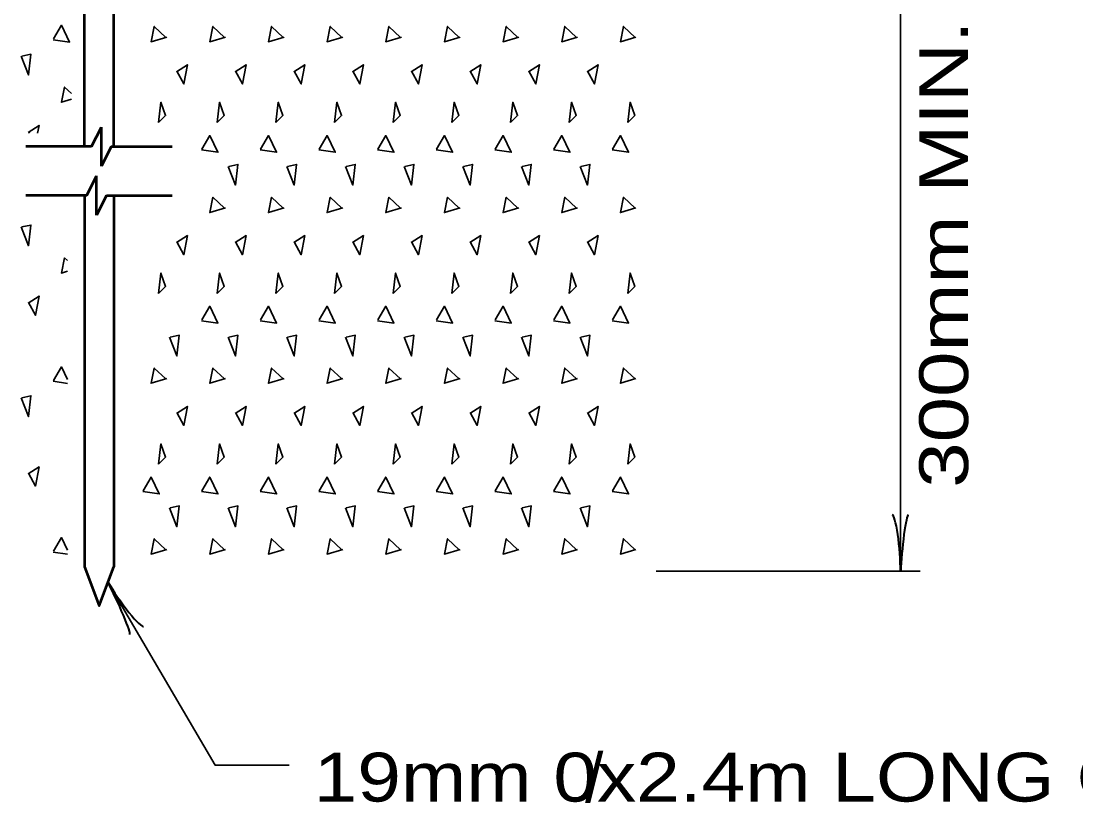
# Model space of a CAD drawing. Extents: x 918 to 1774, y -8 to 536.
# Drawn here: x 1102.6 to 1167.4, y 94.3 to 142.4 of the extents above; entities that cross this region are included whole.
import ezdxf

# ---------------------------------------------------------------- set-up
doc = ezdxf.new("R2010")
doc.units = 0
doc.header["$LTSCALE"] = 1.2
doc.layers.add('1', color=7, linetype='Continuous', lineweight=35)

msp = doc.modelspace()

# ---------------------------------------------------------------- linework, layer by layer
at = {"layer": '1', "lineweight": 53}
for p, q in [((1108.328, 134.643), (1108.328, 176.343)), ((1106.977, 134.643), (1107.578, 135.843)), ((1107.578, 133.443), (1107.578, 135.843)), ((1106.977, 134.643), (1102.928, 134.643)), ((1108.178, 134.643), (1107.578, 133.443)), ((1108.178, 134.643), (1111.928, 134.643)), ((1106.678, 131.643), (1107.278, 132.843)), ((1107.278, 130.443), (1107.278, 132.843)), ((1106.678, 131.643), (1102.928, 131.643)), ((1106.528, 131.643), (1106.528, 108.843)), ((1107.878, 131.643), (1107.278, 130.443)), ((1107.878, 131.643), (1111.928, 131.643)), ((1108.328, 131.643), (1108.328, 108.843))]:
    msp.add_line(p, q, dxfattribs=at)
at = {"layer": '1'}
for p, q in [((1103.102, 135.567), (1103.157, 135.466)), ((1105.493, 120.106), (1104.614, 120.231)), ((1105.493, 109.618), (1104.614, 109.743)), ((1141.628, 108.575), (1157.828, 108.575))]:
    msp.add_line(p, q, dxfattribs=at)
for points in [[(1156.628, 235.047), (1156.628, 170.643), (1156.628, 158.067), (1156.628, 146.075), (1156.628, 108.575)], [(1104.638, 141.255), (1105.118, 142.095), (1105.622, 141.063), (1104.614, 141.207)], [(1111.586, 141.375), (1110.626, 141.087), (1110.818, 142.023), (1111.538, 141.351)], [(1115.186, 141.375), (1114.226, 141.087), (1114.418, 142.023), (1115.138, 141.351)], [(1118.786, 141.375), (1117.826, 141.087), (1118.018, 142.023), (1118.738, 141.351)], [(1122.386, 141.375), (1121.426, 141.087), (1121.618, 142.023), (1122.338, 141.351)], [(1125.986, 141.375), (1125.026, 141.087), (1125.218, 142.023), (1125.938, 141.351)], [(1129.586, 141.375), (1128.626, 141.087), (1128.818, 142.023), (1129.538, 141.351)], [(1133.186, 141.375), (1132.226, 141.087), (1132.418, 142.023), (1133.138, 141.351)], [(1136.786, 141.375), (1135.826, 141.087), (1136.018, 142.023), (1136.738, 141.351)], [(1140.386, 141.375), (1139.426, 141.087), (1139.618, 142.023), (1140.338, 141.351)], [(1102.646, 140.199), (1103.102, 139.047), (1103.246, 140.319), (1102.694, 140.199)], [(1112.21, 139.287), (1112.642, 138.495), (1112.858, 139.671), (1112.186, 139.239)], [(1115.81, 139.287), (1116.242, 138.495), (1116.458, 139.671), (1115.786, 139.239)], [(1119.41, 139.287), (1119.842, 138.495), (1120.058, 139.671), (1119.386, 139.239)], [(1123.01, 139.287), (1123.442, 138.495), (1123.658, 139.671), (1122.986, 139.239)], [(1126.61, 139.287), (1127.042, 138.495), (1127.258, 139.671), (1126.586, 139.239)], [(1130.21, 139.287), (1130.642, 138.495), (1130.858, 139.671), (1130.186, 139.239)], [(1133.81, 139.287), (1134.242, 138.495), (1134.458, 139.671), (1133.786, 139.239)], [(1137.41, 139.287), (1137.842, 138.495), (1138.058, 139.671), (1137.386, 139.239)], [(1105.74, 137.554), (1105.118, 137.367), (1105.31, 138.303), (1105.74, 137.902)], [(1103.661, 135.466), (1103.75, 135.951), (1103.078, 135.519)], [(1113.746, 134.487), (1114.226, 135.327), (1114.73, 134.295), (1113.722, 134.439)], [(1117.346, 134.487), (1117.826, 135.327), (1118.33, 134.295), (1117.322, 134.439)], [(1120.946, 134.487), (1121.426, 135.327), (1121.93, 134.295), (1120.922, 134.439)], [(1124.546, 134.487), (1125.026, 135.327), (1125.53, 134.295), (1124.522, 134.439)], [(1128.146, 134.487), (1128.626, 135.327), (1129.13, 134.295), (1128.122, 134.439)], [(1131.746, 134.487), (1132.226, 135.327), (1132.73, 134.295), (1131.722, 134.439)], [(1135.346, 134.487), (1135.826, 135.327), (1136.33, 134.295), (1135.322, 134.439)], [(1138.946, 134.487), (1139.426, 135.327), (1139.93, 134.295), (1138.922, 134.439)], [(1115.354, 133.431), (1115.81, 132.279), (1115.954, 133.551), (1115.402, 133.431)], [(1118.954, 133.431), (1119.41, 132.279), (1119.554, 133.551), (1119.002, 133.431)], [(1122.554, 133.431), (1123.01, 132.279), (1123.154, 133.551), (1122.602, 133.431)], [(1126.154, 133.431), (1126.61, 132.279), (1126.754, 133.551), (1126.202, 133.431)], [(1129.754, 133.431), (1130.21, 132.279), (1130.354, 133.551), (1129.802, 133.431)], [(1133.354, 133.431), (1133.81, 132.279), (1133.954, 133.551), (1133.402, 133.431)], [(1136.954, 133.431), (1137.41, 132.279), (1137.554, 133.551), (1137.002, 133.431)], [(1115.186, 130.887), (1114.226, 130.599), (1114.418, 131.535), (1115.138, 130.863)], [(1118.786, 130.887), (1117.826, 130.599), (1118.018, 131.535), (1118.738, 130.863)], [(1122.386, 130.887), (1121.426, 130.599), (1121.618, 131.535), (1122.338, 130.863)], [(1125.986, 130.887), (1125.026, 130.599), (1125.218, 131.535), (1125.938, 130.863)], [(1129.586, 130.887), (1128.626, 130.599), (1128.818, 131.535), (1129.538, 130.863)], [(1133.186, 130.887), (1132.226, 130.599), (1132.418, 131.535), (1133.138, 130.863)], [(1136.786, 130.887), (1135.826, 130.599), (1136.018, 131.535), (1136.738, 130.863)], [(1140.386, 130.887), (1139.426, 130.599), (1139.618, 131.535), (1140.338, 130.863)], [(1102.646, 129.711), (1103.102, 128.559), (1103.246, 129.831), (1102.694, 129.711)], [(1112.21, 128.799), (1112.642, 128.007), (1112.858, 129.183), (1112.186, 128.751)], [(1115.81, 128.799), (1116.242, 128.007), (1116.458, 129.183), (1115.786, 128.751)], [(1119.41, 128.799), (1119.842, 128.007), (1120.058, 129.183), (1119.386, 128.751)], [(1123.01, 128.799), (1123.442, 128.007), (1123.658, 129.183), (1122.986, 128.751)], [(1126.61, 128.799), (1127.042, 128.007), (1127.258, 129.183), (1126.586, 128.751)], [(1130.21, 128.799), (1130.642, 128.007), (1130.858, 129.183), (1130.186, 128.751)], [(1133.81, 128.799), (1134.242, 128.007), (1134.458, 129.183), (1133.786, 128.751)], [(1137.41, 128.799), (1137.842, 128.007), (1138.058, 129.183), (1137.386, 128.751)], [(1105.493, 126.992), (1105.118, 126.879), (1105.31, 127.815), (1105.493, 127.644)], [(1103.102, 125.079), (1103.534, 124.287), (1103.75, 125.463), (1103.078, 125.031)], [(1113.746, 123.999), (1114.226, 124.839), (1114.73, 123.807), (1113.722, 123.951)], [(1117.346, 123.999), (1117.826, 124.839), (1118.33, 123.807), (1117.322, 123.951)], [(1120.946, 123.999), (1121.426, 124.839), (1121.93, 123.807), (1120.922, 123.951)], [(1124.546, 123.999), (1125.026, 124.839), (1125.53, 123.807), (1124.522, 123.951)], [(1128.146, 123.999), (1128.626, 124.839), (1129.13, 123.807), (1128.122, 123.951)], [(1131.746, 123.999), (1132.226, 124.839), (1132.73, 123.807), (1131.722, 123.951)], [(1135.346, 123.999), (1135.826, 124.839), (1136.33, 123.807), (1135.322, 123.951)], [(1138.946, 123.999), (1139.426, 124.839), (1139.93, 123.807), (1138.922, 123.951)], [(1111.754, 122.943), (1112.21, 121.791), (1112.354, 123.063), (1111.802, 122.943)], [(1115.354, 122.943), (1115.81, 121.791), (1115.954, 123.063), (1115.402, 122.943)], [(1118.954, 122.943), (1119.41, 121.791), (1119.554, 123.063), (1119.002, 122.943)], [(1122.554, 122.943), (1123.01, 121.791), (1123.154, 123.063), (1122.602, 122.943)], [(1126.154, 122.943), (1126.61, 121.791), (1126.754, 123.063), (1126.202, 122.943)], [(1129.754, 122.943), (1130.21, 121.791), (1130.354, 123.063), (1129.802, 122.943)], [(1133.354, 122.943), (1133.81, 121.791), (1133.954, 123.063), (1133.402, 122.943)], [(1136.954, 122.943), (1137.41, 121.791), (1137.554, 123.063), (1137.002, 122.943)], [(1104.638, 120.279), (1105.118, 121.119), (1105.493, 120.351)], [(1111.586, 120.399), (1110.626, 120.111), (1110.818, 121.047), (1111.538, 120.375)], [(1115.186, 120.399), (1114.226, 120.111), (1114.418, 121.047), (1115.138, 120.375)], [(1118.786, 120.399), (1117.826, 120.111), (1118.018, 121.047), (1118.738, 120.375)], [(1122.386, 120.399), (1121.426, 120.111), (1121.618, 121.047), (1122.338, 120.375)], [(1125.986, 120.399), (1125.026, 120.111), (1125.218, 121.047), (1125.938, 120.375)], [(1129.586, 120.399), (1128.626, 120.111), (1128.818, 121.047), (1129.538, 120.375)], [(1133.186, 120.399), (1132.226, 120.111), (1132.418, 121.047), (1133.138, 120.375)], [(1136.786, 120.399), (1135.826, 120.111), (1136.018, 121.047), (1136.738, 120.375)], [(1140.386, 120.399), (1139.426, 120.111), (1139.618, 121.047), (1140.338, 120.375)], [(1102.646, 119.223), (1103.102, 118.071), (1103.246, 119.343), (1102.694, 119.223)], [(1112.21, 118.311), (1112.642, 117.519), (1112.858, 118.695), (1112.186, 118.263)], [(1115.81, 118.311), (1116.242, 117.519), (1116.458, 118.695), (1115.786, 118.263)], [(1119.41, 118.311), (1119.842, 117.519), (1120.058, 118.695), (1119.386, 118.263)], [(1123.01, 118.311), (1123.442, 117.519), (1123.658, 118.695), (1122.986, 118.263)], [(1126.61, 118.311), (1127.042, 117.519), (1127.258, 118.695), (1126.586, 118.263)], [(1130.21, 118.311), (1130.642, 117.519), (1130.858, 118.695), (1130.186, 118.263)], [(1133.81, 118.311), (1134.242, 117.519), (1134.458, 118.695), (1133.786, 118.263)], [(1137.41, 118.311), (1137.842, 117.519), (1138.058, 118.695), (1137.386, 118.263)], [(1103.102, 114.591), (1103.534, 113.799), (1103.75, 114.975), (1103.078, 114.543)], [(1110.146, 113.511), (1110.626, 114.351), (1111.13, 113.319), (1110.122, 113.463)], [(1113.746, 113.511), (1114.226, 114.351), (1114.73, 113.319), (1113.722, 113.463)], [(1117.346, 113.511), (1117.826, 114.351), (1118.33, 113.319), (1117.322, 113.463)], [(1120.946, 113.511), (1121.426, 114.351), (1121.93, 113.319), (1120.922, 113.463)], [(1124.546, 113.511), (1125.026, 114.351), (1125.53, 113.319), (1124.522, 113.463)], [(1128.146, 113.511), (1128.626, 114.351), (1129.13, 113.319), (1128.122, 113.463)], [(1131.746, 113.511), (1132.226, 114.351), (1132.73, 113.319), (1131.722, 113.463)], [(1135.346, 113.511), (1135.826, 114.351), (1136.33, 113.319), (1135.322, 113.463)], [(1138.946, 113.511), (1139.426, 114.351), (1139.93, 113.319), (1138.922, 113.463)], [(1111.754, 112.455), (1112.21, 111.303), (1112.354, 112.575), (1111.802, 112.455)], [(1115.354, 112.455), (1115.81, 111.303), (1115.954, 112.575), (1115.402, 112.455)], [(1118.954, 112.455), (1119.41, 111.303), (1119.554, 112.575), (1119.002, 112.455)], [(1122.554, 112.455), (1123.01, 111.303), (1123.154, 112.575), (1122.602, 112.455)], [(1126.154, 112.455), (1126.61, 111.303), (1126.754, 112.575), (1126.202, 112.455)], [(1129.754, 112.455), (1130.21, 111.303), (1130.354, 112.575), (1129.802, 112.455)], [(1133.354, 112.455), (1133.81, 111.303), (1133.954, 112.575), (1133.402, 112.455)], [(1136.954, 112.455), (1137.41, 111.303), (1137.554, 112.575), (1137.002, 112.455)], [(1104.638, 109.791), (1105.118, 110.631), (1105.493, 109.863)], [(1111.586, 109.911), (1110.626, 109.623), (1110.818, 110.559), (1111.538, 109.887)], [(1115.186, 109.911), (1114.226, 109.623), (1114.418, 110.559), (1115.138, 109.887)], [(1118.786, 109.911), (1117.826, 109.623), (1118.018, 110.559), (1118.738, 109.887)], [(1122.386, 109.911), (1121.426, 109.623), (1121.618, 110.559), (1122.338, 109.887)], [(1125.986, 109.911), (1125.026, 109.623), (1125.218, 110.559), (1125.938, 109.887)], [(1129.586, 109.911), (1128.626, 109.623), (1128.818, 110.559), (1129.538, 109.887)], [(1133.186, 109.911), (1132.226, 109.623), (1132.418, 110.559), (1133.138, 109.887)], [(1136.786, 109.911), (1135.826, 109.623), (1136.018, 110.559), (1136.738, 109.887)], [(1140.386, 109.911), (1139.426, 109.623), (1139.618, 110.559), (1140.338, 109.887)], [(1107.975, 107.902), (1114.551, 96.665), (1119.103, 96.665)]]:
    msp.add_lwpolyline(points, dxfattribs=at)
at = {"layer": '1', "lineweight": 53}
for points in [[(1106.528, 134.643), (1106.528, 176.343), (1108.328, 176.343)], [(1106.528, 108.843), (1107.428, 106.443), (1108.328, 108.843)]]:
    msp.add_lwpolyline(points, dxfattribs=at)
at = {"layer": '1'}
for points in [[(1111.082, 136.119), (1111.226, 137.367), (1111.514, 136.551)], [(1114.682, 136.119), (1114.826, 137.367), (1115.114, 136.551)], [(1118.282, 136.119), (1118.426, 137.367), (1118.714, 136.551)], [(1121.882, 136.119), (1122.026, 137.367), (1122.314, 136.551)], [(1125.482, 136.119), (1125.626, 137.367), (1125.914, 136.551)], [(1129.082, 136.119), (1129.226, 137.367), (1129.514, 136.551)], [(1132.682, 136.119), (1132.826, 137.367), (1133.114, 136.551)], [(1136.282, 136.119), (1136.426, 137.367), (1136.714, 136.551)], [(1139.882, 136.119), (1140.026, 137.367), (1140.314, 136.551)], [(1111.082, 125.631), (1111.226, 126.879), (1111.514, 126.063)], [(1114.682, 125.631), (1114.826, 126.879), (1115.114, 126.063)], [(1118.282, 125.631), (1118.426, 126.879), (1118.714, 126.063)], [(1121.882, 125.631), (1122.026, 126.879), (1122.314, 126.063)], [(1125.482, 125.631), (1125.626, 126.879), (1125.914, 126.063)], [(1129.082, 125.631), (1129.226, 126.879), (1129.514, 126.063)], [(1132.682, 125.631), (1132.826, 126.879), (1133.114, 126.063)], [(1136.282, 125.631), (1136.426, 126.879), (1136.714, 126.063)], [(1139.882, 125.631), (1140.026, 126.879), (1140.314, 126.063)], [(1111.082, 115.143), (1111.226, 116.391), (1111.514, 115.575)], [(1114.682, 115.143), (1114.826, 116.391), (1115.114, 115.575)], [(1118.282, 115.143), (1118.426, 116.391), (1118.714, 115.575)], [(1121.882, 115.143), (1122.026, 116.391), (1122.314, 115.575)], [(1125.482, 115.143), (1125.626, 116.391), (1125.914, 115.575)], [(1129.082, 115.143), (1129.226, 116.391), (1129.514, 115.575)], [(1132.682, 115.143), (1132.826, 116.391), (1133.114, 115.575)], [(1136.282, 115.143), (1136.426, 116.391), (1136.714, 115.575)], [(1139.882, 115.143), (1140.026, 116.391), (1140.314, 115.575)]]:
    msp.add_lwpolyline(points, close=True, dxfattribs=at)
at = {"layer": '1', "lineweight": 40}
for centre, major_axis, ratio, start_param, end_param in [((1156.296, 109.885), (0.187, -2.143), 0.122415, 0.896353, 3.141593), ((1156.881, 109.92), (-0.211, -2.108), 0.07063, 3.140715, 5.41811), ((1108.435, 106.613), (0.883, -1.926), 0.07063, 6.282307, 8.559703), ((1108.922, 106.939), (-1.244, 1.755), 0.122415, 0.896353, 3.141593)]:
    msp.add_ellipse(centre, major_axis=major_axis, ratio=ratio, start_param=start_param, end_param=end_param, dxfattribs=at)

# ---------------------------------------------------------------- texts
at = {"layer": '1', "width": 1.25}
msp.add_text('300mm MIN.', height=3, rotation=90, dxfattribs=at).set_placement((1160.77, 113.695))
at = {"layer": '1', "width": 1.2}
msp.add_text('19mm 0x2.4m LONG COPPER CLAD GROUND', height=3, dxfattribs=at).set_placement((1120.603, 94.424))
at = {"layer": '1'}
msp.add_text('/', height=3, dxfattribs=at).set_placement((1137.264, 94.383))

doc.saveas('drawing.dxf')
